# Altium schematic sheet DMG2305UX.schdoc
size 127 x 101 mm
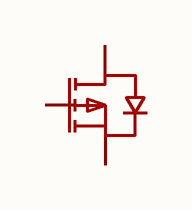
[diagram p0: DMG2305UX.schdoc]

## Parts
Q?  dmg2305ux  [SOT-23-3_L2.9-W1.3-P0.95-LS2.4-BR-1]  (value not drawn)

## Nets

Not connected (* = marked no-connect by the designer): Q? 1(G) 2(S) 3(D)

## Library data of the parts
Q? = dmg2305ux: 数量:1个P沟道;漏源电压(Vdss):20V;连续漏极电流(Id):4.1A;导通电阻(RDS(on)):52mΩ@4.5V;耗散功率(Pd):1.7W;阈值电压(Vgs(th)):1V;; Manufacturer: TECH PUBLIC(台舟); AddInBom: yes; ModelId: ef41b3e5dd9e422d964387bb3b69faa1; ModelTransform: 94.488,114.173,0,0,0,0,0,0,0; Number: 1个P沟道; Drain to Source Voltage: 20V; Current - Continuous Drain(Id): 4.1A; Pd - Power Dissipation: 1.7W; Gate Threshold Voltage (Vgs(th)): 1V; Gate Charge(Qg): 7.8nC; Input Capacitance(Ciss): 740pF; Reverse Transfer Capacitance (Crss@Vds): 190pF; Type: P沟道; Output Capacitance(Coss): 290pF; Vgs: ±12V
